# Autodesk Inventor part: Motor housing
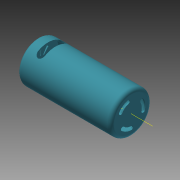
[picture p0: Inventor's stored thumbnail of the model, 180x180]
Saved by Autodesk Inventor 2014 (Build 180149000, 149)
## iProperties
Created: 2008-06
Part Number: Motor housing
Document SubType Name: Modeling
Designer: tangg
Density: 1.13 g/cm^3
Mass: 14.7217 g
Surface Area: 216.806 cm^2
Volume: 14.7217 cm^3
Stock Number: Motor housing
Material: Nylon-6/6
Appearance: Cadet Blue
Author: tangg
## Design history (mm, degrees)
sketch "Sketch1"
  geometry: L1 (0, 0)-(82.55, 0); L2 (0, 0)-(0, 18.503); L3 (82.55, 18.503)-(82.55, 0); L4 (82.55, 18.503)-(82.55, 9.252); L5 (0, 18.503)-(82.55, 18.503); 1 further point
  constraints: 10 end point, 2 horizontal, 2 vertical, 1 midpoint, 1 point on line
  dimensions: "d13" = 82.55 distance of L2.end L3.start
revolve "Revolution1" sketch "Sketch1" stored, may be unused: angle "d0" = 90 deg
fillet "Fillet1" dims "d1" = 3.175
shell "Shell1" dims "d6" = 1.27
sketch "Sketch3"
  geometry: L1 (0, 0)-(10.999, 6.35); L2 (0, 0)-(12.267, -3.287); L3 (8.249, 4.762)-(10.999, 6.35); L4 (9.2, -2.465)-(12.267, -3.287); A1 r 9.525 centre (0, 0) between (9.2, -2.465) and (8.249, 4.762); A2 r 12.7 centre (0, 0) between (12.267, -3.287) and (10.999, 6.35); A3 r 1.588 centre (10.734, -2.876) between (9.2, -2.465) and (12.267, -3.287); 2 further points
  constraints: 8 end point, 6 point on circle, 3 centre point, 2 coincident, 2 midpoint, 2 point on line, 3 other
  dimensions: "d2" = 45 deg angle of L2 L1
extrude "Extrusion1" cut sketch "Sketch3" distance "d3" = 2.54; taper "d4" = 0 deg
workplane "Work Plane2"
sketch "Sketch4"
  geometry: 1 further point
pattern_circular "Circular Pattern1" dims angle "d8" = 360 deg
sketch "Sketch5"
  geometry: 1 further point
sketch "Sketch6"
  geometry: C1 r 17.233 at (0, 0) reference; C2 r 18.503 at (0, 0) reference; 1 further point
extrude "Extrusion2" join sketch "Sketch6" distance "d10" = 2.54; taper "d11" = 0 deg
fillet "Fillet2" dims "d12" = 3.175
sketch "Sketch7"
  geometry: L1 (-6.946, 8.998)-(-6.946, -8.998); L2 (16.51, 0)-(-99.06, 0) reference; L3 (-13.615, 8.731)-(-13.615, -8.731); A1 r 3.345 centre (-10.29, 9.095) between (-6.946, 8.998) and (-13.615, 8.731); A2 r 3.34 centre (-10.275, -8.731) between (-13.615, -8.731) and (-6.946, -8.998); 3 further points
  constraints: 4 end point, 4 point on circle, 2 centre point, 2 midpoint, 2 point on line
extrude "Extrusion3" cut sketch "Sketch7" stored distance "d14" = 25.4; taper "d15" = 0 deg
workplane "Work Plane4"
  workplane "Work Plane3"
sketch "Sketch8"
  geometry: L1 (26.988, -22.225)-(6.565, -22.196); L2 (6.565, -22.196)-(6.57, -19.01); L3 (6.57, -19.01)-(26.992, -19.039); L4 (26.992, -19.039)-(26.988, -22.225); 1 further point
  constraints: 2 other
  dimensions: "d17" = 3.18632 distance of L1.end L2.end; "d18" = 20.42209 distance of L2.end L3.end
emboss "Emboss1" sketch "Sketch8" dims "d19" = 0.254, "d20" = 0
sketch "Sketch9"
  geometry: L1 (0, 0)-(1.167, 14.833); L2 (0, 0)-(-1.266, 16.086); L3 (0, 25.904)-(0, -25.904) reference; L4 (-0.374, 4.748)-(-0.875, 11.113); L5 (0.374, 4.748)-(0.875, 11.113); A1 r 4.763 centre (0, 0) between (-0.374, 4.748) and (0.374, 4.748); A2 r 11.147 centre (0, 0) between (0.875, 11.113) and (-0.875, 11.113); A3 r 4.762 centre (0, 0) between (0.374, 4.748) and (-0.374, 4.748); 1 further point
  constraints: 8 end point, 6 point on circle, 4 point on line, 3 centre point, 2 coincident, 3 other
  dimensions: "d21" = 9 deg angle of L1 L2; "d22" = 4.5 deg angle of L1 L3
extrude "Extrusion4" cut sketch "Sketch9" stored distance "d23" = 10; taper "d24" = 0 deg
pattern_circular "Circular Pattern2" dims angle "d26" = 360 deg
body "Solid1"
workaxis "Work Axis1"
workaxis "Work Axis2"
node "Projected Loop1"
other parameters: "d5" = -3.81, "d16" = 60 deg
